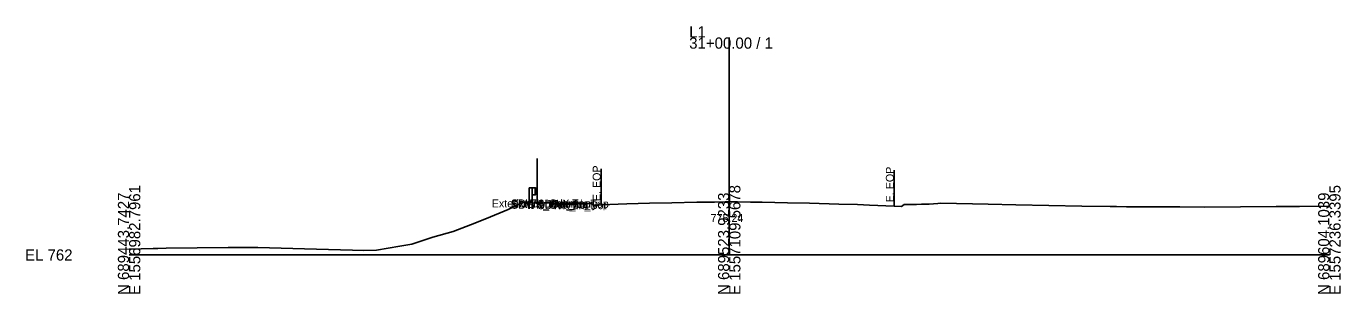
# Model space of a CAD drawing. Extents: x -26 to 2603, y -3010 to 9589.
# Drawn here: x 974.3 to 1302.8, y 4490.3 to 4557.2 of the extents above; entities that cross this region are included whole.
import ezdxf

# ---------------------------------------------------------------- set-up
doc = ezdxf.new("R2010")
doc.units = 0
for name, color, linetype in [('Default', 7, 'Continuous'), ('Exist Cross Section Cell', 7, 'Continuous'), ('Exist XS Center Line Elevation Label', 7, 'Continuous'), ('Exist XS Ground Line', 7, 'Continuous'), ('Prop CMT Conc Surface', 7, 'Continuous'), ('Prop CMT Concrete Structures', 7, 'Continuous'), ('Prop CMT Slope Grass', 7, 'Continuous'), ('Prop XS Earthwork Shape', 7, 'Continuous'), ('Prop XS Label Text', 7, 'Continuous'), ('Scratch_Level_1', 7, 'Continuous'), ('Typical Guardrail CELL', 7, 'Continuous')]:
    doc.layers.add(name, color=color, linetype=linetype)

msp = doc.modelspace()

# ---------------------------------------------------------------- linework, layer by layer
at = {"layer": 'Exist Cross Section Cell'}
for p, q in [((1150, 4500), (1150, 4554.38)), ((1000, 4500), (1150, 4500)), ((1150, 4500), (1300, 4500))]:
    msp.add_line(p, q, dxfattribs=at)
at = {"layer": 'Exist XS Ground Line'}
msp.add_lwpolyline([(1000, 4501.47), (1006.04, 4501.6), (1007.16, 4501.64), (1009.27, 4501.69), (1024.8, 4501.84), (1029.34, 4501.85), (1032.21, 4501.83), (1043.84, 4501.53), (1055.87, 4501.21), (1058.5, 4501.13), (1061.8, 4501.22), (1067.7, 4502.21), (1070.69, 4502.68), (1075.92, 4504.42), (1081.04, 4505.85), (1085.34, 4507.52), (1089.31, 4509.14), (1094.78, 4511.38), (1098.61, 4513.21), (1101.66, 4512.94), (1103.78, 4513.04), (1105, 4513.02), (1105.66, 4512.97), (1113.66, 4512.72), (1115.46, 4512.89), (1115.83, 4512.65), (1116.13, 4512.44), (1117.01, 4512.49), (1117.98, 4512.55), (1124.4, 4512.76), (1130.07, 4512.96), (1135.64, 4513.05), (1141.94, 4513.17), (1143.98, 4513.2), (1146.29, 4513.23), (1148.97, 4513.25), (1150, 4513.25), (1152.06, 4513.25), (1155.3, 4513.23), (1158.24, 4513.21), (1164.57, 4513.04), (1170.1, 4512.93), (1177.37, 4512.71), (1182.08, 4512.58), (1185.08, 4512.45), (1191.26, 4512.23), (1193.05, 4512.13), (1193.73, 4512.64), (1196.83, 4512.63), (1198.05, 4512.72), (1199.97, 4512.73), (1202.16, 4512.88), (1202.86, 4512.93), (1214.69, 4512.69), (1221.6, 4512.55), (1238.15, 4512.24), (1245.19, 4512.09), (1246.78, 4512.09), (1249.3, 4512.07), (1262.02, 4512.04), (1262.67, 4512.04), (1268.85, 4511.98), (1286.71, 4512.08), (1290.27, 4512.09), (1292.52, 4512.13), (1300, 4512.17)], dxfattribs=at)
at = {"layer": 'Prop CMT Conc Surface'}
msp.add_line((1111.51, 4512.93), (1106.51, 4512.98), dxfattribs=at)
at = {"layer": 'Prop CMT Concrete Structures'}
msp.add_line((1111.51, 4512.6), (1106.51, 4512.65), dxfattribs=at)
for points in [[(1106.51, 4512.65), (1106.51, 4512.98)], [(1111.51, 4512.93), (1111.51, 4512.6)]]:
    msp.add_lwpolyline(points, dxfattribs=at)
at = {"layer": 'Prop CMT Slope Grass'}
for p, q in [((1106.51, 4512.98), (1105.33, 4512.99)), ((1111.51, 4512.93), (1115.46, 4512.89))]:
    msp.add_line(p, q, dxfattribs=at)
at = {"layer": 'Prop XS Earthwork Shape'}
for points in [[(1105.33, 4512.99), (1105.66, 4512.97), (1106.51, 4512.94), (1106.51, 4512.98)], [(1106.51, 4512.94), (1111.51, 4512.79), (1111.51, 4512.6), (1106.51, 4512.65)], [(1111.51, 4512.93), (1115.46, 4512.89), (1113.66, 4512.72), (1111.51, 4512.79)]]:
    msp.add_lwpolyline(points, close=True, dxfattribs=at)
at = {"layer": 'Prop XS Label Text'}
for p, q in [((1117.98, 4521.55), (1117.98, 4512.55)), ((1191.26, 4521.23), (1191.26, 4512.23))]:
    msp.add_line(p, q, dxfattribs=at)
at = {"layer": 'Scratch_Level_1'}
msp.add_line((1102, 4513.24), (1102, 4524.11), dxfattribs=at)
at = {"layer": 'Typical Guardrail CELL'}
for p, q in [((1100.77, 4516.81), (1100.02, 4516.81)), ((1100.02, 4516.81), (1100.02, 4513.08)), ((1100.77, 4516.81), (1100.77, 4513.08)), ((1100.77, 4516.81), (1101.52, 4516.81)), ((1100.77, 4515.07), (1101.52, 4515.07)), ((1101.52, 4516.81), (1101.52, 4515.07)), ((1101.52, 4516.81), (1101.95, 4516.5)), ((1101.52, 4516.01), (1101.95, 4516.31)), ((1101.52, 4515.94), (1101.52, 4516.01)), ((1101.52, 4515.94), (1101.52, 4515.87)), ((1101.52, 4515.87), (1101.95, 4515.56)), ((1101.52, 4515.07), (1101.95, 4515.37)), ((1100.77, 4513.08), (1100.02, 4513.08)), ((1100.02, 4513.08), (1100.02, 4511.57)), ((1100.77, 4513.08), (1100.77, 4511.57))]:
    msp.add_line(p, q, dxfattribs=at)
for centre, start, end in [((1101.88, 4516.41), 304.9888, 54.997), ((1101.88, 4515.47), 304.9634, 54.9941)]:
    msp.add_arc(centre, 0.116, start, end, dxfattribs=at)

# ---------------------------------------------------------------- texts
at = {"layer": 'Default'}
for s, height, p in [('Exterior Boundary', 2, (1090.65, 4511.89)), ('SDWK_Out_Top', 2, (1095.44, 4511.89)), ('SDWK_Out_Bot', 2, (1095.47, 4511.55)), ('Exterior Boundary', 2, (1095.65, 4511.79)), ('SDWK_In_Top', 2, (1102.06, 4511.79)), ('SDWK_In_Bot', 2, (1102.09, 4511.45)), ('-', 0.0001, (1000, 4500))]:
    msp.add_text(s, height=height, dxfattribs=at).set_placement(p)
at = {"layer": 'Exist Cross Section Cell'}
for s, p in [('L1', (1140, 4554.38)), ('31+00.00 / 1', (1140, 4551.58)), ('EL 762', (974, 4498.6))]:
    msp.add_text(s, height=2.8, dxfattribs=at).set_placement(p)
for s, p in [('E 1557236.3395', (1302.8, 4490)), ('N 689443.7427', (1000, 4490)), ('E 1556982.7961', (1002.8, 4490)), ('N 689523.9233', (1150, 4490)), ('E 1557109.5678', (1152.8, 4490)), ('N 689604.1039', (1300, 4490))]:
    msp.add_text(s, height=2.8, rotation=90, dxfattribs=at).set_placement(p)
at = {"layer": 'Exist XS Center Line Elevation Label'}
msp.add_text('775.24', height=2, dxfattribs=at).set_placement((1145.35, 4508.24))
at = {"layer": 'Prop XS Label Text'}
for p in [(1117.88, 4513.47), (1191.16, 4513.16)]:
    msp.add_text('E. EOP', height=2, rotation=90, dxfattribs=at).set_placement(p)

doc.saveas('drawing.dxf')
